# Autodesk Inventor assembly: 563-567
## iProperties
Author: Administrator
Shininess: 64.0
Angle Display Precision: 2
Document Length Units: 11272
Document Angle Units: 11286
Document Time Units: 11279
Document Mass Units: 11290
Document Length Units Precision: 3
Document Angle Units Precision: 2
Compacted: True
PropertySet Name: _Private Model Information
Created: 2002-03
Part Number: 563-567
Document SubType Name: Assembly
Designer: Administrator
Control State: 0
Master: False
Checked Out: False
PropertySet Name: Design Tracking Control
Density: 0.0
Volumn: 0.0
Area: 0.0
PropertySet Name: Model Information
